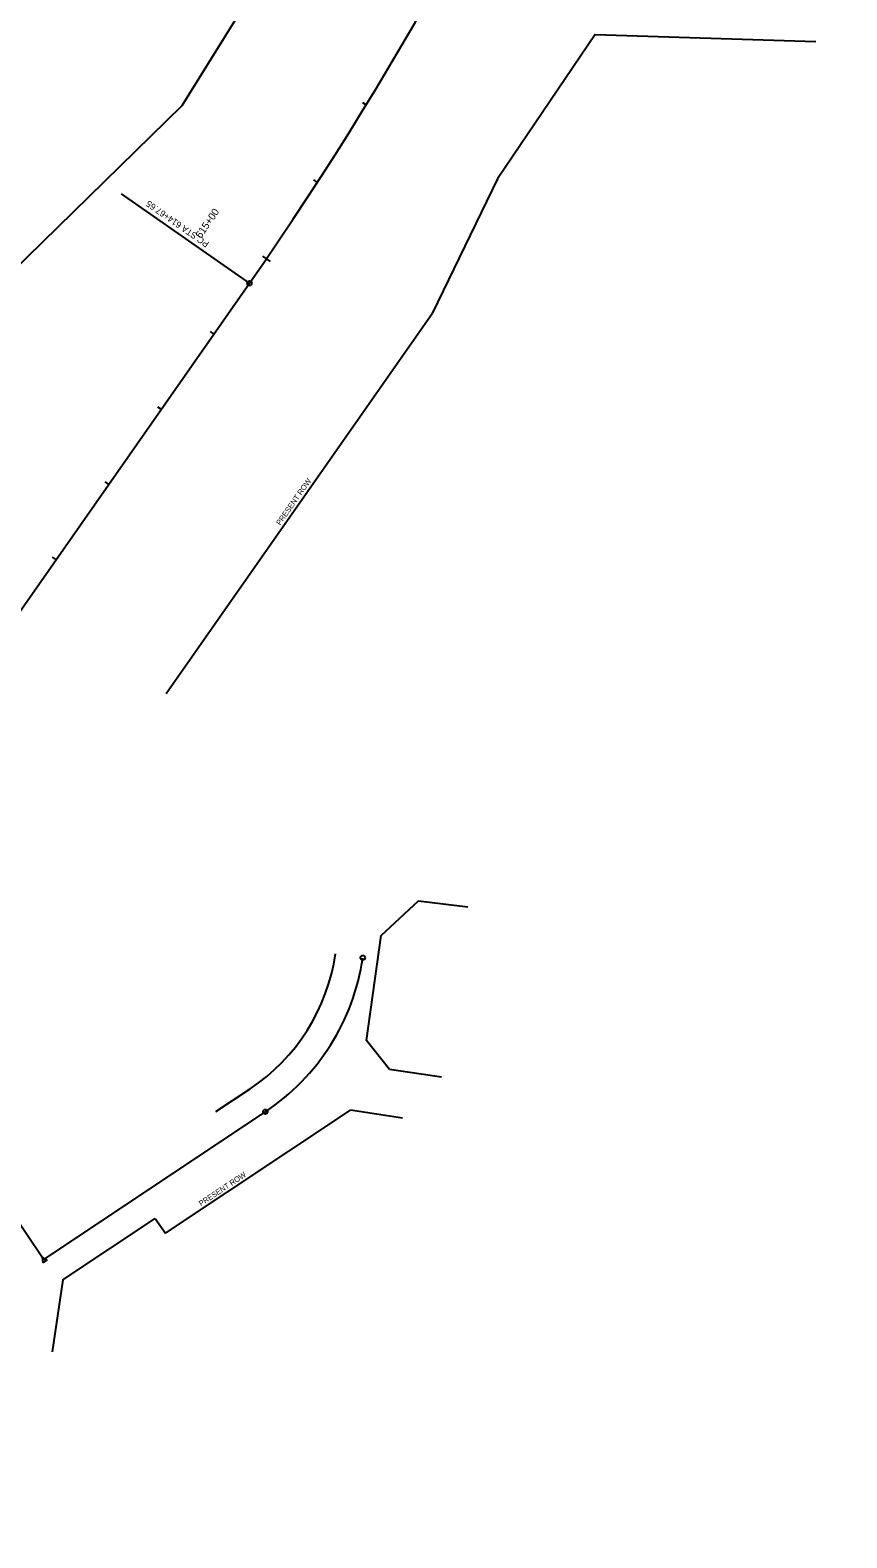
# Model space of a CAD drawing. Extents: x 1790419 to 1799551, y 243603 to 252255.
# Drawn here: x 1796721 to 1797610, y 243678 to 245321 of the extents above; entities that cross this region are included whole.
import ezdxf

# ---------------------------------------------------------------- set-up
doc = ezdxf.new("R2010")
doc.units = 0
for name, color, linetype in [('CL-CNST', 7, 'Continuous'), ('CL-CNSTTXT', 7, 'Continuous'), ('Default', 7, 'Continuous'), ('Prop_Horiz Alignment', 7, 'Continuous'), ('PRP_ROW', 7, 'Continuous'), ('PRPROWTXT', 7, 'Continuous'), ('Survey BL', 7, 'Continuous')]:
    doc.layers.add(name, color=color, linetype=linetype)

msp = doc.modelspace()

# ---------------------------------------------------------------- linework, layer by layer
at = {"layer": 'CL-CNST'}
for points in [[(1797082.7, 245241.8), (1797086.9, 245239.2)], [(1797029.4, 245157.3), (1797033.6, 245154.6)], [(1796974, 245074.3), (1796982.2, 245068.6)], [(1796916.8, 244992.3), (1796920.9, 244989.4)], [(1796859.5, 244910.3), (1796863.6, 244907.4)], [(1796802.2, 244828.4), (1796806.3, 244825.5)], [(1796744.9, 244746.4), (1796749, 244743.5)]]:
    msp.add_lwpolyline(points, dxfattribs=at)
at = {"layer": 'CL-CNSTTXT'}
msp.add_lwpolyline([(1796959.7, 245044.8), (1796820.3, 245142.3)], dxfattribs=at)
at = {"layer": 'Default'}
for p, q in [((1796003.6, 243677.7), (1796959.7, 245044.8)), ((1796735.6, 243981.1), (1796977, 244142))]:
    msp.add_line(p, q, dxfattribs=at)
for centre, radius, start, end in [((1793829.3, 247233.7), 3819.7, 325.0377, 351.8556), ((1796841.7, 244345), 244, 303.6901, 351.6921)]:
    msp.add_arc(centre, radius, start, end, dxfattribs=at)
at = {"layer": 'Prop_Horiz Alignment'}
msp.add_lwpolyline([(1796734.2, 243983.1), (1796739.1, 243980.4), (1796734.9, 243977.6)], close=True, dxfattribs=at)
for centre in [(1796959.7, 245044.8), (1797083.1, 244309.8), (1796977, 244142)]:
    msp.add_circle(centre, 2.5, dxfattribs=at)
at = {"layer": 'PRP_ROW'}
for p, q in [((1796886.4, 245238.3), (1797050.9, 245503.6)), ((1797336.4, 245316), (1797230, 245158.7)), ((1797336.4, 245316), (1797576.6, 245308.3)), ((1796536.7, 244896.7), (1796886.4, 245238.3)), ((1797230, 245158.7), (1797158.6, 245011.8)), ((1796869, 244597.7), (1797158.6, 245011.8)), ((1797103.3, 244333.9), (1797144, 244371.8)), ((1797144, 244371.8), (1797197.6, 244365.4)), ((1797087.2, 244219.7), (1797103.3, 244333.9)), ((1797112.1, 244187.9), (1797087.2, 244219.7)), ((1797168.8, 244179.5), (1797112.1, 244187.9)), ((1796923.1, 244142.1), (1796960.4, 244167)), ((1796868.3, 244009.5), (1797069.6, 244143.6)), ((1797126.5, 244135.1), (1797069.6, 244143.6)), ((1796756.4, 243958.9), (1796856.8, 244025.8)), ((1796856.8, 244025.8), (1796868.3, 244009.5)), ((1796756.4, 243958.9), (1796744.8, 243880.4))]:
    msp.add_line(p, q, dxfattribs=at)
msp.add_arc((1796841.7, 244345), 214, 303.69, 351.6894, dxfattribs=at)
at = {"layer": 'Survey BL'}
for p, q in [((1796003.6, 243677.7), (1796959.7, 245044.8)), ((1796735.6, 243981.1), (1796977, 244142)), ((1796695.7, 244040.5), (1796735.6, 243981.1))]:
    msp.add_line(p, q, dxfattribs=at)
for centre, radius, start, end in [((1793829.3, 247233.7), 3819.7, 325.0377, 351.8556), ((1796841.7, 244345), 244, 303.6901, 351.6921)]:
    msp.add_arc(centre, radius, start, end, dxfattribs=at)

# ---------------------------------------------------------------- texts
at = {"layer": 'CL-CNSTTXT'}
for s, height, rotation, p in [('PC STA 614+67.65', 7, 145.0347, (1796916.4, 245089.1)), ('615+00', 8, 55.523, (1796906.8, 245093.1))]:
    msp.add_text(s, height=height, rotation=rotation, dxfattribs=at).set_placement(p)
at = {"layer": 'PRPROWTXT'}
for rotation, p in [(55.0347, (1796993.2, 244780.5)), (33.6911, (1796907, 244038.8))]:
    msp.add_text('PRESENT ROW', height=6, rotation=rotation, dxfattribs=at).set_placement(p)

doc.saveas('drawing.dxf')
